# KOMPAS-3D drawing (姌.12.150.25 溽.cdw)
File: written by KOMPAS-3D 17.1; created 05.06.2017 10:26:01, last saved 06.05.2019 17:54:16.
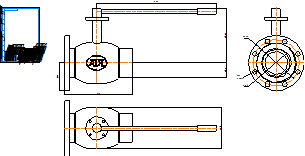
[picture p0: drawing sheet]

Sheet 1: A4, portrait

Title block, sheet 1: name: КШ.12.150.25 фс; material: Внимание! Данный продукт является объектом авторского права ООО «Торговый Дом АДЛ». / Запрещается изменение, копирование, распространение / (в том числе путем копирования на другие сайты и ресурсы в Интернете) / или любое иное использование информации и объектов без предварительного / согласия правообладателя (ООО «Торговый Дом АДЛ»).; sheets: 1; organisation: ООО "Торговый дом АДЛ"; sheet format: A4; stored path: C:\Users\kka\KOMPAS_Work\Модели кранов для исследований\Все краники\Редуцированный резьба-сварка ШК БИВАЛ\КШ.02.015.40 рс.cdw

Views: Вид 1, Проекционный вид 2, Проекционный вид 3
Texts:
  Klimkovich
  ADL
Dimensions and other numbers on the sheet: 645; 370; 291,6; 79,5; 250; 150; 149; 26; 8 Отв.; 219; 1:1; 1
